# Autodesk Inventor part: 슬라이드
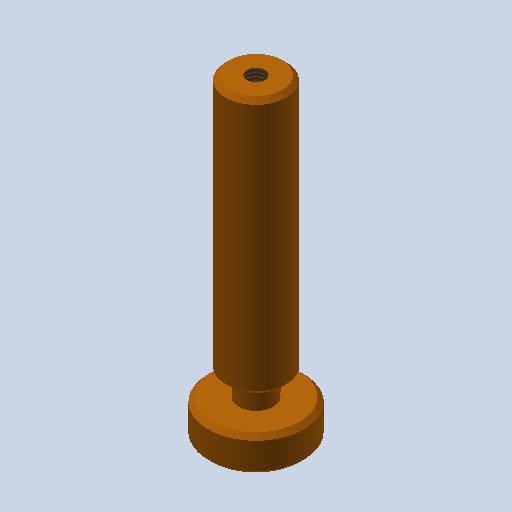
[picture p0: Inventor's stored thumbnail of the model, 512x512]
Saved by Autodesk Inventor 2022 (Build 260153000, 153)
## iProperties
Created: 2015-09
Part Number: 슬라이드
Material: 강철, 연강
Document SubType Name: Modeling
Designer: mduedu
Density: 1 g/cm^3
Appearance: 주황색
Author: mduedu
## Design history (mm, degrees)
sketch "스케치1"
  geometry: C1 r 11 at (0, 0); 1 further point
  constraints: 1 centre point, 1 coincident
  dimensions: "d0" = 22 diameter of C1
extrude "돌출1" new body sketch "스케치1" distance "d1" = 8; taper "d2" = 0 deg
sketch "스케치2"
  geometry: C1 r 4 at (0, 0); 1 further point
  constraints: 1 centre point, 1 coincident
  dimensions: "d3" = 8 diameter of C1
extrude "돌출2" join sketch "스케치2" distance "d4" = 5; taper "d5" = 0 deg
sketch "스케치3"
  geometry: C1 r 7 at (0, 0); 1 further point
  constraints: 1 centre point, 1 coincident
  dimensions: "d6" = 14 diameter of C1
extrude "돌출3" join sketch "스케치3" distance "d7" = 59; taper "d8" = 0 deg
hole "구멍1" diameter "d11" = 4.134; stored, may be unused: countersink angle "d15" = 90 deg, drill point angle "d17" = 118 deg; dims "d9" = 10, "d10" = 10, "d12" = 9, "d13" = 4, "d14" = 2, "d16" = 12
chamfer "모따기1" distance "d18" = 1; stored, may be unused: second distance "d19" = 2, angle "d20" = 45 deg
node "솔리드1"
